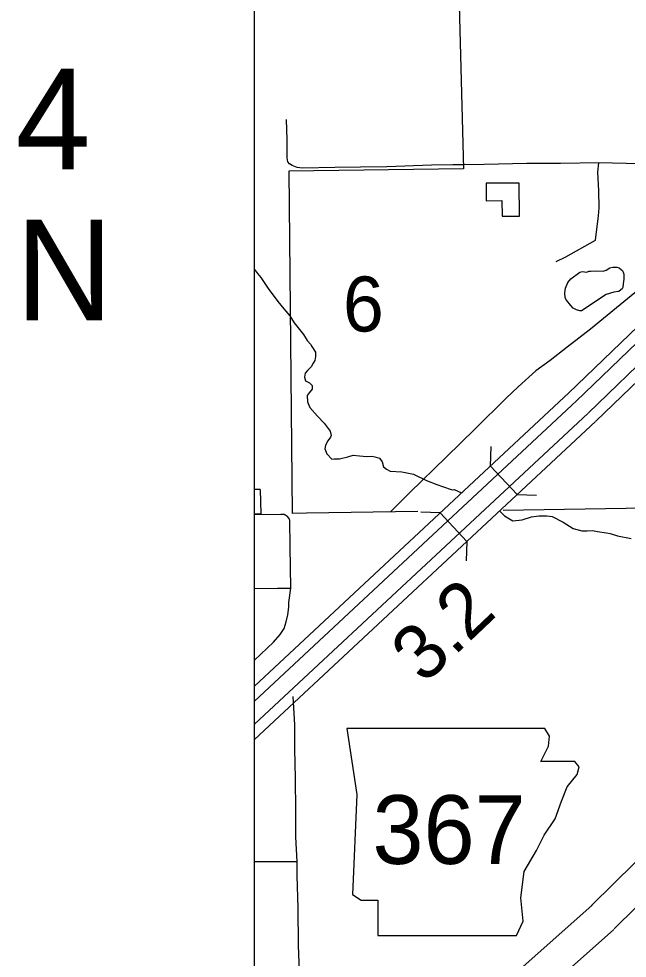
# Model space of a CAD drawing. Extents: x 1367863 to 1368197, y 380048 to 380261.
# Drawn here: x 1367952.41 to 1367970.56, y 380131.45 to 380159.47 of the extents above; entities that cross this region are included whole.
import ezdxf

# ---------------------------------------------------------------- set-up
doc = ezdxf.new("R2010")
doc.units = 0
for name, color, linetype in [('Level 10', 7, 'Continuous'), ('Level 15', 7, 'Continuous'), ('Level 21', 7, 'Continuous'), ('Level 31', 7, 'Continuous'), ('Level 33', 7, 'Continuous'), ('Level 35', 7, 'Continuous'), ('Level 36', 7, 'Continuous'), ('Level 48', 7, 'Continuous'), ('Level 5', 7, 'Continuous'), ('Level 58', 7, 'Continuous'), ('Level 6', 7, 'Continuous'), ('R_Draft', 7, 'Continuous'), ('R_No Plot', 7, 'Continuous')]:
    doc.layers.add(name, color=color, linetype=linetype)

msp = doc.modelspace()

# ---------------------------------------------------------------- linework, layer by layer
at = {"layer": 'Level 10'}
for points in [[(1367969.491, 380133.018), (1367971.441, 380134.938)], [(1367972.114, 380134.239), (1367970.172, 380132.327)], [(1367959.444, 380123.965), (1367960.435, 380125.172), (1367960.622, 380125.358), (1367960.839, 380125.604), (1367961.127, 380125.881), (1367961.296, 380126.009), (1367961.763, 380126.42), (1367963.132, 380127.482), (1367964.116, 380128.267), (1367964.487, 380128.603), (1367964.936, 380128.963), (1367969.509, 380133.035)], [(1367970.154, 380132.31), (1367965.562, 380128.221), (1367965.116, 380127.864), (1367964.745, 380127.528), (1367963.732, 380126.72), (1367962.381, 380125.672), (1367961.91, 380125.257), (1367961.759, 380125.142), (1367961.54, 380124.932), (1367961.328, 380124.692), (1367961.153, 380124.518), (1367959.444, 380122.436)]]:
    msp.add_lwpolyline(points, dxfattribs=at)
at = {"layer": 'Level 15'}
for points in [[(1367981.823, 380158.812), (1367978.861, 380156.604), (1367974.211, 380153.076), (1367973.061, 380152.177), (1367971.993, 380151.299), (1367970.884, 380150.3), (1367968.811, 380148.303)], [(1367969.039, 380148.066), (1367971.109, 380150.058), (1367972.208, 380151.049), (1367973.268, 380151.92), (1367974.413, 380152.815), (1367979.059, 380156.34), (1367981.956, 380158.5)], [(1367969.389, 380147.702), (1367971.453, 380149.689), (1367972.537, 380150.666), (1367973.583, 380151.526), (1367974.721, 380152.415), (1367979.362, 380155.937), (1367982.096, 380157.975)], [(1367982.189, 380157.633), (1367979.561, 380155.673), (1367974.922, 380152.154), (1367973.79, 380151.269), (1367972.752, 380150.416), (1367971.678, 380149.448), (1367969.618, 380147.465)], [(1367959.444, 380139.567), (1367968.817, 380148.31)], [(1367969.042, 380148.069), (1367959.444, 380139.115)], [(1367959.444, 380138.426), (1367969.386, 380147.7)], [(1367969.611, 380147.458), (1367959.444, 380137.974)]]:
    msp.add_lwpolyline(points, dxfattribs=at)
at = {"layer": 'Level 21'}
msp.add_lwpolyline([(1367962.201, 380138.302), (1367962.497, 380136.333), (1367962.365, 380133.345), (1367962.628, 380133.181), (1367963.12, 380133.181), (1367963.12, 380132.13), (1367967.257, 380132.13), (1367967.454, 380132.557), (1367967.388, 380133.247), (1367967.487, 380134.035), (1367967.848, 380134.658), (1367968.078, 380135.118), (1367968.406, 380135.61), (1367968.603, 380136.136), (1367968.767, 380136.562), (1367969.063, 380136.924), (1367969.128, 380137.153), (1367968.997, 380137.317), (1367967.979, 380137.317), (1367968.209, 380137.777), (1367968.242, 380138.073), (1367968.106, 380138.299)], close=True, dxfattribs=at)
at = {"layer": 'Level 31'}
for points in [[(1367969.713, 380155.17), (1367968.571, 380155.156), (1367967.56, 380155.156), (1367966.293, 380155.122), (1367965.675, 380155.116)], [(1367968.441, 380152.226), (1367968.729, 380152.37), (1367969.617, 380152.866), (1367969.7, 380153.592), (1367969.717, 380153.825), (1367969.708, 380154.337), (1367969.679, 380154.894), (1367969.713, 380155.17)], [(1367974.548, 380154.873), (1367974.498, 380154.973), (1367974.427, 380155.073), (1367974.32, 380155.144), (1367974.214, 380155.164), (1367973.414, 380155.148), (1367972.16, 380155.132), (1367971.438, 380155.137), (1367970.529, 380155.154), (1367969.713, 380155.17)], [(1367974.548, 380154.873), (1367974.185, 380154.61), (1367973.972, 380154.411), (1367973.688, 380154.098), (1367973.361, 380153.686), (1367972.948, 380153.145), (1367972.65, 380152.776), (1367972.465, 380152.619), (1367972.038, 380152.278), (1367971.114, 380151.567), (1367970.347, 380150.941), (1367969.465, 380150.215), (1367968.768, 380149.675), (1367968.257, 380149.277), (1367967.83, 380148.964), (1367967.304, 380148.494), (1367966.949, 380148.153), (1367966.024, 380147.243), (1367965.157, 380146.389), (1367964.077, 380145.337), (1367963.508, 380144.774)]]:
    msp.add_lwpolyline(points, dxfattribs=at)
at = {"layer": 'Level 33'}
for points in [[(1367965.673, 380155.116), (1367965.354, 380155.114), (1367964.72, 380155.101), (1367963.389, 380155.054), (1367962.607, 380155.042), (1367961.837, 380155.033), (1367960.875, 380155.008), (1367960.714, 380155.033), (1367960.562, 380155.088), (1367960.486, 380155.143), (1367960.439, 380155.198), (1367960.414, 380155.325), (1367960.418, 380155.856), (1367960.401, 380156.469)], [(1367960.53, 380142.481), (1367960.507, 380143.725), (1367960.499, 380144.504), (1367960.476, 380144.565), (1367960.415, 380144.633), (1367960.377, 380144.656), (1367960.324, 380144.679), (1367960.225, 380144.679), (1367959.444, 380144.673)], [(1367959.444, 380142.476), (1367960.126, 380142.489), (1367960.53, 380142.481)], [(1367959.444, 380140.339), (1367960.013, 380140.874), (1367960.211, 380141.102), (1367960.327, 380141.287), (1367960.388, 380141.477), (1367960.437, 380141.687), (1367960.469, 380141.917), (1367960.468, 380142.061), (1367960.53, 380142.481)], [(1367960.585, 380139.252), (1367960.634, 380138.406), (1367960.641, 380137.687), (1367960.659, 380136.82), (1367960.67, 380135.849), (1367960.67, 380135.067), (1367960.702, 380134.32)], [(1367960.702, 380134.32), (1367960.093, 380134.323), (1367959.444, 380134.32)], [(1367960.702, 380134.32), (1367960.703, 380133.913), (1367960.732, 380132.946), (1367960.749, 380131.842), (1367960.82, 380129.997), (1367960.855, 380129.315), (1367960.912, 380128.815), (1367960.929, 380128.674)]]:
    msp.add_lwpolyline(points, dxfattribs=at)
at = {"layer": 'Level 35'}
for points in [[(1367959.444, 380151.991), (1367959.531, 380151.871), (1367959.628, 380151.749), (1367959.848, 380151.42), (1367960.138, 380151.032), (1367960.318, 380150.813)], [(1367968.697, 380151.295), (1367968.717, 380151.438), (1367968.788, 380151.601), (1367968.879, 380151.711), (1367969.143, 380151.907), (1367969.224, 380151.926), (1367969.289, 380151.916), (1367969.351, 380151.913), (1367969.413, 380151.936), (1367969.475, 380151.942), (1367969.637, 380151.946), (1367969.845, 380151.939), (1367969.93, 380151.975), (1367970.04, 380152.043), (1367970.125, 380152.06), (1367970.245, 380152.056), (1367970.317, 380152.037), (1367970.385, 380151.985), (1367970.428, 380151.936), (1367970.454, 380151.848), (1367970.46, 380151.698), (1367970.434, 380151.562), (1367970.424, 380151.458), (1367970.405, 380151.415), (1367970.372, 380151.386), (1367970.304, 380151.331)], [(1367970.304, 380151.331), (1367970.154, 380151.318), (1367969.93, 380151.243), (1367969.637, 380151.051), (1367969.276, 380150.804), (1367969.195, 380150.758), (1367969.14, 380150.758), (1367969.048, 380150.791), (1367968.951, 380150.836), (1367968.873, 380150.914), (1367968.743, 380151.08), (1367968.71, 380151.145), (1367968.697, 380151.295)], [(1367960.318, 380150.813), (1367960.499, 380150.606), (1367960.622, 380150.4), (1367960.906, 380150.051), (1367961.015, 380149.871), (1367961.118, 380149.761), (1367961.157, 380149.696)], [(1367961.157, 380149.696), (1367961.267, 380149.522), (1367961.267, 380149.393), (1367961.247, 380149.277), (1367961.196, 380149.193), (1367961.131, 380149.09), (1367961.028, 380148.98), (1367960.951, 380148.903), (1367960.931, 380148.78), (1367960.964, 380148.67), (1367961.086, 380148.612), (1367961.164, 380148.535), (1367961.164, 380148.425), (1367961.073, 380148.315), (1367961.015, 380148.231), (1367961.028, 380148.044), (1367961.093, 380147.877), (1367961.325, 380147.618), (1367961.518, 380147.412), (1367961.699, 380147.173), (1367961.731, 380147.044), (1367961.705, 380146.986), (1367961.634, 380146.876), (1367961.557, 380146.754), (1367961.538, 380146.644), (1367961.602, 380146.495), (1367961.751, 380146.334), (1367961.815, 380146.341), (1367961.976, 380146.341), (1367962.228, 380146.405), (1367962.383, 380146.45), (1367962.576, 380146.437), (1367962.789, 380146.412), (1367962.938, 380146.424), (1367963.028, 380146.399), (1367963.17, 380146.36), (1367963.254, 380146.25), (1367963.286, 380146.108), (1367963.376, 380146.037), (1367963.486, 380145.979), (1367963.841, 380145.96), (1367964.189, 380145.889), (1367964.57, 380145.702), (1367964.879, 380145.579), (1367965.047, 380145.515), (1367965.337, 380145.418), (1367965.402, 380145.431), (1367965.621, 380145.328)], [(1367966.773, 380144.77), (1367966.898, 380144.639), (1367967.146, 380144.498), (1367967.429, 380144.521), (1367967.7, 380144.616), (1367967.924, 380144.643), (1367968.157, 380144.643), (1367968.318, 380144.624), (1367968.647, 380144.45), (1367968.95, 380144.263), (1367969.208, 380144.198), (1367969.363, 380144.192), (1367969.524, 380144.204), (1367969.673, 380144.179), (1367969.937, 380144.14), (1367970.053, 380144.121), (1367970.272, 380144.05), (1367970.672, 380143.966)]]:
    msp.add_lwpolyline(points, dxfattribs=at)
at = {"layer": 'Level 36'}
for p, q in [((1367966.479, 380146.129), (1367966.499, 380146.711)), ((1367966.479, 380146.129), (1367967.273, 380145.277)), ((1367967.273, 380145.277), (1367967.855, 380145.257)), ((1367964.981, 380144.731), (1367964.399, 380144.751)), ((1367965.775, 380143.88), (1367964.981, 380144.731)), ((1367965.775, 380143.88), (1367965.754, 380143.298))]:
    msp.add_line(p, q, dxfattribs=at)
at = {"layer": 'Level 58'}
msp.add_lwpolyline([(1367967.337, 380154.569), (1367966.351, 380154.562), (1367966.355, 380154.042), (1367966.822, 380154.045), (1367966.825, 380153.58), (1367967.344, 380153.583)], close=True, dxfattribs=at)
at = {"layer": 'Level 6'}
for points in [[(1367965.424, 380164.398), (1367965.677, 380154.995)], [(1367965.677, 380154.995), (1367960.471, 380154.928)], [(1367960.471, 380154.928), (1367960.57, 380144.713)], [(1367959.612, 380145.426), (1367959.444, 380145.424)], [(1367959.612, 380145.426), (1367959.631, 380144.699)], [(1367971.136, 380144.869), (1367966.858, 380144.806)], [(1367959.631, 380144.699), (1367959.444, 380144.696)], [(1367964.316, 380144.768), (1367960.998, 380144.719), (1367960.57, 380144.713)]]:
    msp.add_lwpolyline(points, dxfattribs=at)
at = {"layer": 'R_No Plot'}
msp.add_lwpolyline([(1367959.444, 380177.46), (1368103.344, 380177.46), (1368103.344, 380096.865), (1367959.444, 380096.865)], close=True, dxfattribs=at)

# ---------------------------------------------------------------- texts
at = {"layer": 'Level 21'}
msp.add_text('367', height=2.0492, dxfattribs=at).set_placement((1367962.96, 380134.261))
at = {"layer": 'Level 48'}
msp.add_text('3.2', height=1.6394, rotation=43.6172, dxfattribs=at).set_placement((1367964.503, 380139.593))
at = {"layer": 'Level 5'}
msp.add_text('6', height=1.639, dxfattribs=at).set_placement((1367962.081, 380150.142))
at = {"layer": 'R_Draft'}
for s, p in [('4', (1367952.323, 380154.976)), ('N', (1367952.323, 380150.476))]:
    msp.add_text(s, height=3, dxfattribs=at).set_placement(p)

doc.saveas('drawing.dxf')
